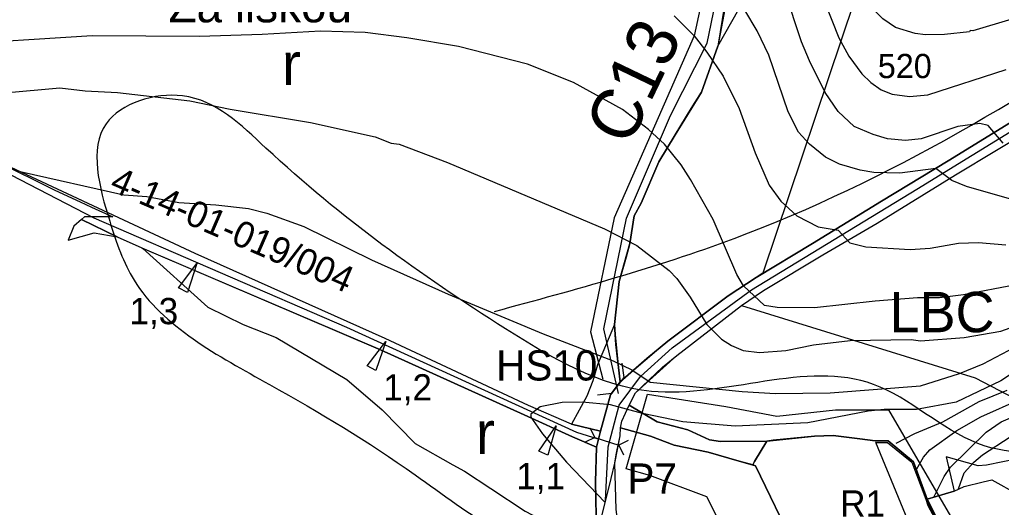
# Model space of a CAD drawing. Extents: x -684583 to -680383, y -1157874 to -1154904.
# Drawn here: x -684293.9 to -683807, y -1157579 to -1157337.4 of the extents above; entities that cross this region are included whole.
import ezdxf

# ---------------------------------------------------------------- set-up
doc = ezdxf.new("R2010")
doc.units = 0
for name, color, linetype in [('01_DOPRAVA', 7, 'Continuous'), ('01_MÍSTNÍ_NÁZVY', 7, 'Continuous'), ('01_OBVOD PÚ', 7, 'Continuous'), ('01_SPRÁV_HRANICE', 7, 'Continuous'), ('01_VRSTEVNICE', 7, 'Continuous'), ('02_KULTURY NÁVRH', 7, 'Continuous'), ('02_KULTURY STAV', 7, 'Continuous'), ('03_PC_OBJEKTY_NÁVRH', 7, 'Continuous'), ('03_PC_OBJEKTY_STAV', 7, 'Continuous'), ('03_PC_POPIS_STAV', 7, 'Continuous'), ('03_PC_STAV', 7, 'Continuous'), ('05_VHO_V_NÁDRŽ_STAV', 7, 'Continuous'), ('05_VHO_V_TOK', 7, 'Continuous'), ('06_BIOGEOGRAFIE', 7, 'Continuous'), ('06_CHR_ÚZEMÍ', 7, 'Continuous'), ('06_ÚSES_BC', 7, 'Continuous'), ('06_ÚSES_BK', 7, 'Continuous')]:
    doc.layers.add(name, color=color, linetype=linetype)

msp = doc.modelspace()

# ---------------------------------------------------------------- linework, layer by layer
at = {"layer": '01_DOPRAVA'}
msp.add_lwpolyline([(-684003.32, -1157575.72), (-684001.96, -1157549.03), (-683996.62, -1157528.36), (-683985.95, -1157514.27), (-683970.28, -1157499.96), (-683930.88, -1157471.22), (-683848.9, -1157421.35), (-683768.73, -1157372.16)], dxfattribs=at)
at = {"layer": '01_OBVOD PÚ'}
for points in [[(-684305.22, -1157407.64), (-684276.36, -1157421.86), (-684263.88, -1157427.58), (-684258.18, -1157430.25), (-684247.66, -1157435.08), (-684261.73, -1157435.02), (-684263.19, -1157436.34), (-684267, -1157439.77), (-684269.76, -1157446.59), (-684256.88, -1157442.94), (-684245.58, -1157444.98), (-684233.35, -1157450.46), (-684232.75, -1157450.77), (-684200.52, -1157479.78), (-684183.11, -1157488.47), (-684166.66, -1157494.83), (-684131.56, -1157515.67), (-684114.05, -1157530.64), (-684097.73, -1157547.47), (-684079.06, -1157557.93), (-684073.33, -1157561.13), (-684060.2, -1157569.77), (-684043.19, -1157580.94)], [(-684005.36, -1157584), (-684000.57, -1157564.75), (-683998.71, -1157557.08), (-683997.72, -1157551.32), (-683996.05, -1157543.53), (-683995.96, -1157539.61), (-683980.96, -1157543.81), (-683969.31, -1157548.24), (-683952.5, -1157551.69), (-683936.99, -1157556.11), (-683928.98, -1157558.4), (-683909.28, -1157599.04)], [(-683835.12, -1157592.28), (-683842.98, -1157577.56), (-683843.76, -1157574.97), (-683830.5, -1157571.05), (-683825.48, -1157568.66), (-683816.01, -1157566.38), (-683811.79, -1157565.45), (-683798.66, -1157572.65)]]:
    msp.add_lwpolyline(points, dxfattribs=at)
at = {"layer": '01_SPRÁV_HRANICE'}
for points in [[(-684305.22, -1157407.64), (-684276.36, -1157421.86), (-684263.88, -1157427.58), (-684258.18, -1157430.25), (-684247.66, -1157435.08), (-684261.73, -1157435.02), (-684263.19, -1157436.34), (-684267, -1157439.77), (-684269.76, -1157446.59), (-684256.88, -1157442.94), (-684245.58, -1157444.98), (-684233.35, -1157450.46), (-684232.75, -1157450.77), (-684200.52, -1157479.78), (-684183.11, -1157488.47), (-684166.66, -1157494.83), (-684131.56, -1157515.67), (-684114.05, -1157530.64), (-684097.73, -1157547.47), (-684079.06, -1157557.93), (-684073.33, -1157561.13), (-684060.2, -1157569.77), (-684043.19, -1157580.94)], [(-684005.36, -1157584), (-684000.57, -1157564.75), (-683998.71, -1157557.08), (-683997.72, -1157551.32), (-683996.05, -1157543.53), (-683995.96, -1157539.61), (-683980.96, -1157543.81), (-683969.31, -1157548.24), (-683952.5, -1157551.69), (-683936.99, -1157556.11), (-683928.98, -1157558.4), (-683909.28, -1157599.04)], [(-683835.12, -1157592.28), (-683842.98, -1157577.56), (-683843.76, -1157574.97), (-683830.5, -1157571.05), (-683825.48, -1157568.66), (-683816.01, -1157566.38), (-683811.79, -1157565.45), (-683798.66, -1157572.65)]]:
    msp.add_lwpolyline(points, dxfattribs=at)
at = {"layer": '01_VRSTEVNICE'}
for points in [[(-683806.22, -1157154.17), (-683812.35, -1157160.74), (-683825.47, -1157173), (-683860.42, -1157203.1), (-683876.83, -1157218.22), (-683888.24, -1157230.77), (-683895.51, -1157241.76), (-683900.79, -1157254.03), (-683903.22, -1157263.3), (-683903.93, -1157268.72), (-683903.93, -1157282.41), (-683899.22, -1157309.8), (-683894.94, -1157328.06), (-683887.67, -1157346.32), (-683882.67, -1157355.45), (-683876.26, -1157364.15), (-683871.69, -1157368.43), (-683866.56, -1157372.13), (-683861.14, -1157374.27), (-683852.58, -1157375.41), (-683843.45, -1157374.56), (-683804.65, -1157362.01)], [(-683801.8, -1157337.19), (-683821.2, -1157342.89), (-683822.48, -1157342.75), (-683822.76, -1157343.32), (-683835.17, -1157344.75), (-683844.59, -1157344.89), (-683849.72, -1157344.18), (-683859.57, -1157341.18), (-683865.84, -1157337.04), (-683872.4, -1157330.34), (-683877.83, -1157321.78), (-683883.53, -1157308.09), (-683885.95, -1157297.82), (-683887.53, -1157280.41), (-683886.24, -1157268.43), (-683884.96, -1157262.44), (-683882.25, -1157254.45), (-683877.97, -1157246.46), (-683869.41, -1157234.48), (-683860.42, -1157224.21), (-683840.59, -1157205.38), (-683809.5, -1157178.71), (-683803.51, -1157172.58)], [(-683806.08, -1157398.52), (-683813.63, -1157389.82), (-683817.77, -1157388.82), (-683828.61, -1157390.25), (-683846.87, -1157396.38), (-683854.57, -1157397.24), (-683863.42, -1157396.38), (-683870.66, -1157394.25), (-683879.96, -1157390.39), (-683887.95, -1157382.83), (-683894.37, -1157373.42), (-683902.22, -1157357.73), (-683906.21, -1157348.31), (-683914.34, -1157323.21)], [(-683802.94, -1157426.2), (-683824.33, -1157420.06), (-683831.61, -1157417.07), (-683839.45, -1157411.08), (-683857.43, -1157413.36), (-683870.26, -1157413.07), (-683877.11, -1157411.93), (-683887.38, -1157408.94), (-683894.23, -1157405.51), (-683902.22, -1157399.09), (-683907.64, -1157393.1), (-683912.77, -1157383.12), (-683922.33, -1157354.88), (-683928.18, -1157342.89), (-683934.31, -1157332.62)], [(-683969.26, -1157335.47), (-683959.42, -1157345.46), (-683953.14, -1157353.45), (-683945.01, -1157365.43), (-683937.02, -1157381.41), (-683929.18, -1157403.37), (-683922.19, -1157419.35), (-683916.34, -1157427.34), (-683908.49, -1157434.61), (-683897.94, -1157440.03), (-683887.95, -1157441.6), (-683882.25, -1157447.88), (-683874.26, -1157450.02), (-683852.29, -1157451.3), (-683842.31, -1157450.59), (-683828.33, -1157448.16), (-683818.34, -1157447.74), (-683804.79, -1157448.88)], [(-683799.8, -1157468.85), (-683825.76, -1157473.7), (-683837.74, -1157475.27), (-683848.58, -1157475.27), (-683869.69, -1157476.83), (-683899.65, -1157480.12), (-683918.19, -1157479.97), (-683924.47, -1157478.97), (-683934.88, -1157469.28), (-683938.16, -1157463.57), (-683950, -1157436.47), (-683961.13, -1157416.5), (-683965.84, -1157409.36), (-683974.11, -1157399.09), (-683982.1, -1157391.82), (-683994.94, -1157381.83), (-684019.18, -1157368.57), (-684042.01, -1157359.44), (-684076.24, -1157350.59), (-684101.92, -1157346.32), (-684122.46, -1157343.75), (-684144.71, -1157343.03), (-684173.53, -1157344.75), (-684204.62, -1157345.74), (-684257.97, -1157345.46), (-684331.29, -1157350.02)], [(-684301.33, -1157373.7), (-684273.95, -1157371.14), (-684261.4, -1157372.56), (-684245.42, -1157373.42), (-684209.47, -1157377.55), (-684189.5, -1157381.69), (-684149.56, -1157388.25), (-684117.61, -1157395.38), (-684109.62, -1157398.52), (-684105.63, -1157399.09), (-684081.66, -1157408.22), (-684003.78, -1157441.03), (-683987.8, -1157449.3), (-683971.83, -1157461.71), (-683967.98, -1157465.71), (-683961.41, -1157474.84), (-683953.14, -1157488.39), (-683945.87, -1157495.66), (-683940.87, -1157498.8), (-683935.03, -1157501.23), (-683927.04, -1157502.37), (-683913.91, -1157501.23), (-683900.22, -1157498.52), (-683881.96, -1157496.38), (-683851.72, -1157495.81), (-683847.16, -1157496.52), (-683825.47, -1157494.95), (-683807.22, -1157491.67), (-683798.51, -1157488.53)], [(-684293.69, -1157412.63), (-684242.28, -1157424.2), (-684230.87, -1157425.05), (-684214.89, -1157428.05), (-684196.63, -1157429.05), (-684180.37, -1157430.9), (-684171.24, -1157433.19), (-684152.98, -1157439.89), (-684119.32, -1157456.44), (-684081.38, -1157473.41), (-684034.3, -1157493.1), (-683999.5, -1157506.36), (-683990.37, -1157510.93), (-683981.24, -1157517.06), (-683935.6, -1157521.62), (-683919.05, -1157522.62), (-683891.95, -1157522.34), (-683847.16, -1157518.77), (-683827.76, -1157512.78), (-683816.06, -1157507.93), (-683790.95, -1157494.66)], [(-683784.68, -1157501.23), (-683807.36, -1157516.35), (-683829.47, -1157526.9), (-683849.15, -1157530.61), (-683865.13, -1157530.61), (-683873.12, -1157531.32), (-683903.07, -1157537.17), (-683939.02, -1157538.74), (-683964.98, -1157536.6), (-683984.95, -1157532.61), (-684000.93, -1157528.19), (-684014.91, -1157526.9), (-684024.89, -1157527.05), (-684035.73, -1157529.18), (-684040.3, -1157532.89), (-684040.3, -1157534.32), (-684034.59, -1157542.59), (-684022.61, -1157556.57), (-684003.46, -1157576.66)], [(-683859.28, -1157547.3), (-683850.01, -1157542.45), (-683836.03, -1157536.6), (-683818.06, -1157526.62), (-683804.08, -1157520.91)], [(-683849.01, -1157560), (-683845.73, -1157554.15), (-683842.45, -1157550.58), (-683829.18, -1157541.03), (-683817.2, -1157534.18), (-683797.23, -1157525.19)], [(-683832.18, -1157559.14), (-683814.63, -1157541.74), (-683807.07, -1157536.74), (-683785.53, -1157527.33)], [(-683828.33, -1157569.84), (-683825.47, -1157561.99), (-683820.62, -1157556.57), (-683816.34, -1157553.01), (-683802.65, -1157544.16)], [(-683840.51, -1157574.01), (-683835.46, -1157563.71), (-683832.18, -1157559.14)]]:
    msp.add_lwpolyline(points, dxfattribs=at)
at = {"layer": '02_KULTURY NÁVRH'}
msp.add_lwpolyline([(-683869.3, -1157546.93), (-683863.45, -1157546.93), (-683851.41, -1157556.62), (-683844.52, -1157575.06), (-683843.52, -1157578.18), (-683835.91, -1157592.16), (-683839.46, -1157598.61), (-683846.87, -1157601.42)], close=True, dxfattribs=at)
at = {"layer": '02_KULTURY STAV'}
for points in [[(-683940.7, -1157313.6), (-683947.59, -1157350.45), (-683955.69, -1157373.26), (-683968.87, -1157394.43), (-683976.94, -1157407.83), (-683985.68, -1157428.23), (-683989.06, -1157434.53), (-683991.24, -1157448.33), (-683996.64, -1157467.19), (-683998.85, -1157488.48), (-684007.33, -1157508.48), (-684009.58, -1157516.35), (-684012.59, -1157523.97), (-684020.21, -1157537.76), (-684041.56, -1157528.62), (-684112.57, -1157495.44), (-684206.82, -1157453.3), (-684320.88, -1157400.08)], [(-683944.31, -1157330.16), (-683947.59, -1157350.45), (-683955.69, -1157373.26), (-683961.65, -1157382.65), (-683968.87, -1157394.43), (-683976.94, -1157407.83), (-683985.68, -1157428.23), (-683989.06, -1157434.53), (-683991.24, -1157448.33), (-683993.15, -1157454.99), (-683996.64, -1157467.19), (-683998.85, -1157488.48), (-683998.28, -1157498.32), (-683996.04, -1157516.81), (-683982.82, -1157505.23), (-683972.51, -1157496.68), (-683942.47, -1157474.27), (-683928.66, -1157465.07), (-683900.62, -1157448.32), (-683866.55, -1157427.35), (-683833.42, -1157407.25), (-683789.54, -1157380.46)], [(-683789.54, -1157380.46), (-683833.42, -1157407.25), (-683866.55, -1157427.35), (-683900.62, -1157448.32), (-683928.66, -1157465.07), (-683942.47, -1157474.27), (-683972.51, -1157496.68), (-683996.04, -1157516.81), (-684000.82, -1157523.31), (-684005.87, -1157541.29), (-684007.75, -1157549.2), (-684008.36, -1157566.31), (-684007.87, -1157591.8)], [(-684005.36, -1157584), (-684000.57, -1157564.75), (-683998.71, -1157557.08), (-683997.98, -1157552.95), (-683997.72, -1157551.32), (-683996.05, -1157543.53), (-683995.96, -1157539.61), (-683995.22, -1157536.37), (-683991.62, -1157528.32), (-683988.41, -1157522.23), (-683968.01, -1157503.73), (-683935.87, -1157479.03), (-683925.07, -1157471.54), (-683895.49, -1157453.83), (-683868.57, -1157438.18), (-683829.77, -1157414.19), (-683809.4, -1157402.02), (-683784.34, -1157387.05)], [(-683798.27, -1157554.84), (-683814.37, -1157558.12), (-683818.47, -1157558.47), (-683834.35, -1157554.07), (-683830.5, -1157571.05), (-683843.76, -1157574.97), (-683850.56, -1157556.47), (-683863.17, -1157546), (-683869.62, -1157546.12), (-683877.23, -1157545), (-683890.5, -1157543.45), (-683899.65, -1157543.8), (-683920.12, -1157545.75), (-683923.3, -1157546.22), (-683946.3, -1157546.36), (-683951.73, -1157545.58), (-683962.57, -1157540.58), (-683977.72, -1157536.72), (-683991.62, -1157528.32), (-683988.41, -1157522.23), (-683968.01, -1157503.73), (-683935.87, -1157479.03), (-683925.07, -1157471.54), (-683895.49, -1157453.83), (-683868.57, -1157438.18), (-683829.77, -1157414.19), (-683809.4, -1157402.02), (-683784.34, -1157387.05)], [(-684305.22, -1157407.64), (-684276.36, -1157421.86), (-684263.88, -1157427.58), (-684258.18, -1157430.25), (-684247.66, -1157435.08), (-684261.73, -1157435.02), (-684263.19, -1157436.34), (-684245.58, -1157444.98), (-684233.35, -1157450.46), (-684114.86, -1157500.94), (-684043.74, -1157533.23), (-684019.72, -1157544.1), (-684007.75, -1157549.2), (-684005.87, -1157541.29), (-684020.21, -1157537.76), (-684041.56, -1157528.62), (-684112.57, -1157495.44), (-684206.82, -1157453.3), (-684320.88, -1157400.08)]]:
    msp.add_lwpolyline(points, dxfattribs=at)
for points in [[(-684263.19, -1157436.34), (-684267, -1157439.77), (-684269.76, -1157446.59), (-684256.88, -1157442.94), (-684245.58, -1157444.98)], [(-684232.75, -1157450.77), (-684200.52, -1157479.78), (-684183.11, -1157488.47), (-684166.66, -1157494.83), (-684131.56, -1157515.67), (-684114.05, -1157530.64), (-684097.73, -1157547.47), (-684079.06, -1157557.93), (-684073.33, -1157561.13), (-684060.2, -1157569.77), (-684043.19, -1157580.94), (-684028.3, -1157588.68), (-684014.9, -1157590.79), (-684007.87, -1157591.8), (-684008.36, -1157566.31), (-684007.75, -1157549.2), (-684019.72, -1157544.1), (-684043.74, -1157533.23), (-684043.74, -1157533.23), (-684114.86, -1157500.94)], [(-684000.82, -1157523.31), (-683996.04, -1157516.81), (-683998.28, -1157498.32), (-683998.85, -1157488.48), (-684007.33, -1157508.48), (-684009.58, -1157516.35), (-684012.59, -1157523.97), (-684020.21, -1157537.76), (-684005.87, -1157541.29)], [(-683991.62, -1157528.32), (-683977.72, -1157536.72), (-683962.57, -1157540.58), (-683951.73, -1157545.58), (-683946.3, -1157546.36), (-683923.3, -1157546.22), (-683929.49, -1157556.27), (-683930.27, -1157558.03), (-683936.99, -1157556.11), (-683952.5, -1157551.69), (-683969.31, -1157548.24), (-683980.96, -1157543.81), (-683995.96, -1157539.61), (-683995.22, -1157536.37)], [(-683928.98, -1157558.4), (-683930.27, -1157558.03), (-683929.49, -1157556.27), (-683923.3, -1157546.22), (-683899.65, -1157543.8), (-683890.5, -1157543.45), (-683877.23, -1157545), (-683869.62, -1157546.12), (-683863.17, -1157546), (-683850.56, -1157556.47), (-683843.76, -1157574.97), (-683835.12, -1157592.28), (-683839.02, -1157599.34), (-683851.86, -1157603.77), (-683872.16, -1157613.61), (-683885.48, -1157612.56), (-683895.04, -1157609.84), (-683904.82, -1157604.36), (-683909.28, -1157599.04)], [(-683834.35, -1157554.07), (-683830.5, -1157571.05), (-683825.48, -1157568.66), (-683816.01, -1157566.38), (-683811.79, -1157565.45), (-683798.66, -1157572.65), (-683770.44, -1157570.08), (-683746.99, -1157568.73), (-683735.06, -1157569.33), (-683710.91, -1157564.65), (-683683.27, -1157572.53), (-683671.45, -1157557.75), (-683678.58, -1157555.32), (-683694.45, -1157563.21), (-683710.65, -1157559.6), (-683725.15, -1157559.89), (-683746.09, -1157555.07), (-683753.02, -1157549.74), (-683762, -1157549.64), (-683768.48, -1157552.07), (-683789.95, -1157556.75), (-683798.27, -1157554.84), (-683814.37, -1157558.12), (-683818.47, -1157558.47)]]:
    msp.add_lwpolyline(points, close=True, dxfattribs=at)
at = {"layer": '03_PC_OBJEKTY_NÁVRH'}
msp.add_lwpolyline([(-683943.86, -1157192.93), (-683940.03, -1157262.66), (-683949.99, -1157301.75), (-683959.42, -1157345.46), (-683977.31, -1157386.04), (-683999.01, -1157435.6), (-684010.76, -1157492.05), (-684004.63, -1157515.56)], dxfattribs=at)
at = {"layer": '03_PC_OBJEKTY_STAV'}
for points in [[(-683995.18, -1157507.63), (-683994.26, -1157514.64), (-684000.34, -1157522.57), (-684007.35, -1157523.5)], [(-684011.08, -1157539.65), (-684008.67, -1157544.38), (-684013.4, -1157546.78)], [(-684008.67, -1157544.38), (-683996.79, -1157548.25)], [(-683992.06, -1157545.85), (-683996.79, -1157548.25), (-683994.39, -1157552.98)]]:
    msp.add_lwpolyline(points, dxfattribs=at)
at = {"layer": '03_PC_STAV'}
msp.add_lwpolyline([(-683996.97, -1157522.67), (-684004.23, -1157490.53), (-683992.87, -1157435.78), (-683971.07, -1157384.89), (-683952.89, -1157348.98), (-683942.46, -1157298.55), (-683932.92, -1157262.66), (-683938.83, -1157176.33)], dxfattribs=at)
at = {"layer": '05_VHO_V_TOK'}
for points in [[(-684485.8, -1157349.07), (-684390.19, -1157380.48), (-684298.19, -1157414.2), (-684257.11, -1157435.56)], [(-684257.11, -1157435.56), (-684131.77, -1157489.8), (-684017.8, -1157541.82), (-684007.12, -1157545.11)]]:
    msp.add_lwpolyline(points, dxfattribs=at)
for points in [[(-684210.58, -1157472.61), (-684215.03, -1157470.32), (-684205.95, -1157458.12)], [(-684117.22, -1157511.23), (-684121.62, -1157508.86), (-684112.32, -1157496.83)], [(-684031.97, -1157553.25), (-684036.49, -1157551.12), (-684027.85, -1157538.61)]]:
    msp.add_lwpolyline(points, close=True, dxfattribs=at)
at = {"layer": '06_BIOGEOGRAFIE'}
for points in [[(-683662.04, -1156787.77), (-683658.6, -1156877.34), (-683631.05, -1156927.29), (-683541.5, -1156975.52), (-683489.85, -1157028.92), (-683414.08, -1157027.2), (-683362.42, -1157025.48), (-683360.7, -1157063.37), (-683464.02, -1157132.27), (-683493.29, -1157163.28), (-683474.35, -1157189.11), (-683407.19, -1157171.89), (-683317.65, -1157115.05), (-683269.44, -1157104.71), (-683207.44, -1157173.61), (-683186.78, -1157259.74), (-683105.85, -1157416.48), (-683069.69, -1157530.17), (-683073.13, -1157580.12), (-683097.24, -1157628.35), (-683264.27, -1157657.63), (-683431.3, -1157647.3), (-683531.17, -1157605.96), (-683636.21, -1157542.23), (-683651.71, -1157521.56), (-683682.7, -1157519.83), (-683708.53, -1157528.45), (-683818.74, -1157547.39), (-683870.4, -1157518.11), (-683980.6, -1157521.56), (-684052.92, -1157490.55), (-684171.74, -1157400.98), (-684213.07, -1157375.14), (-684250.95, -1157388.92), (-684249.23, -1157437.15), (-684237.17, -1157466.44), (-684170.02, -1157518.11), (-684097.7, -1157562.9), (-684011.6, -1157605.96), (-683953.05, -1157602.51), (-683891.06, -1157626.63), (-683835.96, -1157619.74), (-683789.47, -1157599.07), (-683713.7, -1157578.4), (-683625.88, -1157592.18), (-683551.84, -1157667.97), (-683445.07, -1157736.87), (-683346.92, -1157771.32), (-683179.89, -1157767.87), (-683081.74, -1157773.04), (-683016.71, -1157810.65), (-682999.16, -1157844)], [(-684058.34, -1157481.95), (-683939.53, -1157445.78), (-683724.28, -1157326.93), (-683638.18, -1157271.81), (-683500.43, -1157218.41), (-683460.82, -1157194.29)]]:
    msp.add_spline(points, degree=3, dxfattribs=at)
at = {"layer": '06_CHR_ÚZEMÍ'}
msp.add_lwpolyline([(-683982.45, -1157522.92), (-683943.75, -1157529.02), (-683918.31, -1157533.79), (-683889.23, -1157530.66), (-683873.75, -1157530.66), (-683863.04, -1157530.66), (-683821.86, -1157601.17), (-683850.31, -1157630.6), (-683878.03, -1157634.61), (-683933.37, -1157612.7), (-683953.09, -1157573.86), (-683981.34, -1157563.2), (-683993.16, -1157560.03), (-683982.45, -1157522.92)], dxfattribs=at)
at = {"layer": '06_ÚSES_BC'}
msp.add_lwpolyline([(-683996.09, -1157594.85), (-683998.06, -1157580.14), (-683998.71, -1157557.08), (-683996.05, -1157543.53), (-683995.96, -1157539.61), (-683995.22, -1157536.37), (-683991.62, -1157528.32), (-683988.41, -1157522.23), (-683975.01, -1157509.58), (-683968.01, -1157503.73), (-683935.87, -1157479.03), (-683819.99, -1157514.87), (-683753.02, -1157549.74)], dxfattribs=at)
at = {"layer": '06_ÚSES_BK'}
for points in [[(-683996.04, -1157516.81), (-683998.85, -1157488.48), (-683996.64, -1157467.19), (-683991.24, -1157448.33), (-683989.06, -1157434.53), (-683985.68, -1157428.23), (-683976.94, -1157407.83), (-683968.87, -1157394.43), (-683960.84, -1157381.32), (-683955.69, -1157373.26), (-683947.59, -1157350.45), (-683830.91, -1157144.86), (-683778.26, -1157098.63)], [(-683792.57, -1157198.29), (-683879.8, -1157327.93), (-683925.26, -1157463.04), (-683942.47, -1157474.27), (-683972.51, -1157496.68), (-683982.82, -1157505.23), (-683996.04, -1157516.81)]]:
    msp.add_lwpolyline(points, dxfattribs=at)

# ---------------------------------------------------------------- texts
at = {"layer": '01_MÍSTNÍ_NÁZVY'}
msp.add_text('Za liškou', height=17, dxfattribs=at).set_placement((-684220.01, -1157338.7))
at = {"layer": '01_VRSTEVNICE'}
msp.add_text('520', height=12, dxfattribs=at).set_placement((-683868.31, -1157366.34))
at = {"layer": '02_KULTURY STAV'}
for p in [(-684163.78, -1157369.77), (-684067.61, -1157552.54)]:
    msp.add_text('r', height=21, dxfattribs=at).set_placement(p)
at = {"layer": '03_PC_OBJEKTY_STAV'}
for s, p in [('HS10', (-684057.57, -1157516.18)), ('P7', (-683992.48, -1157572.29))]:
    msp.add_text(s, height=15, dxfattribs=at).set_placement(p)
at = {"layer": '03_PC_POPIS_STAV'}
msp.add_text('C13', height=25, rotation=64.3263, dxfattribs=at).set_placement((-683991.7, -1157400.82))
at = {"layer": '05_VHO_V_NÁDRŽ_STAV'}
msp.add_text('R1', height=13, dxfattribs=at).set_placement((-683886.95, -1157583.61))
at = {"layer": '05_VHO_V_TOK'}
msp.add_text('4-14-01-019/004', height=13, rotation=336.5303, dxfattribs=at).set_placement((-684249.88, -1157421.78))
for s, p in [('1,3', (-684239.42, -1157488.28)), ('1,2', (-684113.57, -1157526.06)), ('1,1', (-684047.6, -1157570.05))]:
    msp.add_text(s, height=13, dxfattribs=at).set_placement(p)
at = {"layer": '06_ÚSES_BC'}
msp.add_text('LBC V KOPANINÁCH', height=20, dxfattribs=at).set_placement((-683862.47, -1157492.27))

doc.saveas('drawing.dxf')
